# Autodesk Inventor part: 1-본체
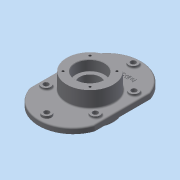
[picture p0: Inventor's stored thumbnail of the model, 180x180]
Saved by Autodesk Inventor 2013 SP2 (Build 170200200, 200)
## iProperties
Created: 2015-02
Part Number: 1-본체
Material: 일반
Document SubType Name: Modeling
Designer: dgall
Density: 1 g/cm^3
Author: dgall
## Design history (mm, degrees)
sketch "스케치2"
  geometry: L1 (-70, 60)-(-70, -60); L2 (-70, -60)-(70, -60); L3 (70, -60)-(70, 60); L4 (70, 60)-(-70, 60); A1 r 74 centre (0, 36) between (70, 60) and (-70, 60); A2 r 74 centre (0, -36) between (-70, -60) and (70, -60); 3 further points
  constraints: 8 end point, 4 point on circle, 3 vertical alignment, 2 centre point, 2 midpoint, 2 parallel, 1 horizontal alignment, 1 perpendicular, 1 vertical
  dimensions: "d4" = 140 distance of L1.end L2.end; "d6" = 120 distance of L2.end L3.end; "d7" = 50 distance edge to line of A1 L4; "d8" = 50 distance edge to line of A2 L2
extrude "돌출1" new body sketch "스케치2" distance "d9" = 12; taper "d10" = 0 deg
fillet "모깎기1" dims "d11" = 3
sketch "스케치3"
  geometry: C1 r 50 at (0, 0); 1 further point
  constraints: 1 centre point, 1 coincident
  dimensions: "d12" = 100 diameter of C1
extrude "돌출2" join sketch "스케치3" distance "d14" = 35; taper "d15" = 0 deg
sketch "스케치4"
  geometry: C1 r 50 at (0, 0); 1 further point
  constraints: 1 centre point, 1 coincident
  dimensions: "d16" = 100 diameter of C1
extrude "돌출3" join sketch "스케치4" distance "d18" = 23; taper "d19" = 0 deg
sketch "스케치5"
  geometry: C1 r 50 at (0, 0) reference; C2 r 31 at (0, 0)
  constraints: 1 centre point, 1 coincident
  dimensions: "d20" = 62 diameter of C2
extrude "돌출4" cut sketch "스케치5" distance "d22" = 22; taper "d23" = 0 deg
sketch "스케치6"
  geometry: C1 r 50 at (0, 0) reference; C2 r 31 at (0, 0)
  constraints: 1 centre point, 1 coincident
  dimensions: "d24" = 62 diameter of C2
extrude "돌출5" cut sketch "스케치6" distance "d26" = 22; taper "d27" = 0 deg
sketch "스케치7"
  geometry: C1 r 31 at (0, 0) reference; C2 r 22.5 at (0, 0)
  constraints: 1 centre point, 1 coincident
  dimensions: "d28" = 45 diameter of C2
extrude "돌출6" cut sketch "스케치7" stored distance "d30" = 22; taper "d31" = 0 deg
sketch "스케치8"
  geometry: L1 (0, 0)-(22.5, 0); L2 (0, 0)-(28.991, 28.991); C1 r 31 at (0, 0) reference; 2 further points
  constraints: 4 end point, 1 coincident, 1 horizontal, 1 horizontal alignment, 1 other
  dimensions: "d33" = 41 distance of L1.start L2.end; "d35" = 45 deg angle of L1 L2
hole "구멍1" sketch "스케치8" at (28.991, 28.991) diameter "d37" = 4.917; stored, may be unused: countersink angle "d41" = 90 deg, drill point angle "d43" = 118 deg; dims "d38" = 10, "d39" = 4, "d40" = 2, "d42" = 13
node "작업 평면1"
fillet "모깎기2" dims "d47" = 0.3
chamfer "모따기1" distance "d48" = 1; stored, may be unused: second distance "d49" = 2, angle "d50" = 45 deg
node "작업 평면2"
sketch "스케치9"
  geometry: 2 further points
  constraints: 1 vertical alignment, 1 other
  dimensions: "d52" = 65 distance of point (0, 0) point (0, 65)
feature "엠보싱1" sketch "스케치9" dims "d16" = 100, "d53" = 1, "d54" = 0
fillet "모깎기3" dims "d55" = 3
sketch "스케치10"
  geometry: L1 (-67, -59.495)-(-67, 59.495) reference; L2 (67, 59.495)-(67, -59.495) reference; L3 (-53, -56.976)-(-53, 56.976); L4 (53, 56.976)-(53, -56.976); L5 (70, -60)-(70, 60) reference; C1 r 10 at (0, -93); C2 r 10 at (0, 93); C3 r 10 at (53, -41.5); C4 r 10 at (-53, -41.5); C5 r 10 at (-53, 41.5); C6 r 10 at (53, 41.5); C7 r 53 at (0, 0) reference; A1 r 71 centre (0, 36) between (67, 59.495) and (-67, 59.495) reference; A2 r 71 centre (0, -36) between (-67, -59.495) and (67, -59.495) reference; A3 r 57 centre (0, -36) between (-53, -56.976) and (53, -56.976); A4 r 57 centre (0, 36) between (53, 56.976) and (-53, 56.976)
  constraints: 8 centre point, 6 point on circle, 4 end point, 4 point on line, 2 equal radius, 2 horizontal alignment, 3 other
  dimensions: "d56" = 17 distance between parallel lines of L4 L5; "d57" = 20 diameter of C2; "d59" = 20 diameter of C5; "d61" = 20 diameter of C4; "d62" = 20 diameter of C6; "d125" = 83 distance of C4.centre C5.centre; "d126" = 41.5 vertical distance of C7.centre C4.centre (= 0.5 x d125)
extrude "돌출7" join sketch "스케치10" distance "d63" = 5; taper "d64" = 0 deg
hole "구멍2" diameter "d67" = 11; stored, may be unused: countersink angle "d71" = 90 deg, drill point angle "d73" = 0 deg; dims "d68" = 10, "d69" = 4, "d70" = 2, "d72" = 13, "d92" = 10, "d93" = 10
hole "구멍3" diameter "d76" = 11; stored, may be unused: countersink angle "d80" = 90 deg, drill point angle "d82" = 0 deg; dims "d77" = 10, "d78" = 4, "d79" = 2, "d81" = 13, "d94" = 10, "d95" = 10
hole "구멍4" diameter "d85" = 11; stored, may be unused: countersink angle "d89" = 90 deg, drill point angle "d91" = 0 deg; dims "d86" = 10, "d87" = 4, "d88" = 2, "d90" = 13, "d96" = 10, "d97" = 10
hole "구멍5" diameter "d100" = 11; stored, may be unused: countersink angle "d104" = 90 deg, drill point angle "d106" = 0 deg; dims "d98" = 10, "d99" = 10, "d101" = 10, "d102" = 4, "d103" = 2, "d105" = 13
hole "구멍6" diameter "d109" = 11; stored, may be unused: countersink angle "d113" = 90 deg, drill point angle "d115" = 0 deg; dims "d107" = 10, "d108" = 10, "d110" = 10, "d111" = 4, "d112" = 2, "d114" = 13
hole "구멍7" diameter "d118" = 11; stored, may be unused: countersink angle "d122" = 90 deg, drill point angle "d124" = 0 deg; dims "d116" = 10, "d117" = 10, "d119" = 10, "d120" = 4, "d121" = 2, "d123" = 13
fillet "모깎기4" dims "d127" = 3
fillet "모깎기5" dims "d128" = 3
node "솔리드1"
pattern_circular "원형 패턴1" dims angle "d45" = 360 deg
mirror "대칭1"
node "투영된 루프1"
